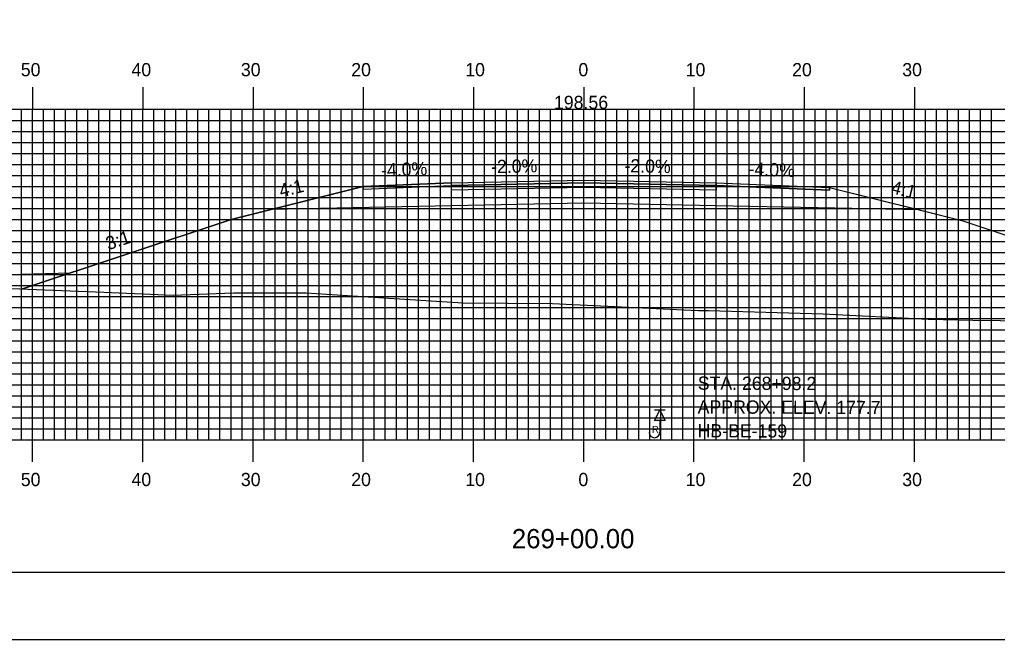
# Model space of a CAD drawing. Extents: x 1808226 to 1808569, y 442591 to 442811.
# Drawn here: x 1808340.1 to 1808428.8, y 442590.5 to 442646.8 of the extents above; entities that cross this region are included whole.
import ezdxf

# ---------------------------------------------------------------- set-up
doc = ezdxf.new("R2010")
doc.units = 0
for name, color, linetype in [('ANNOTATION', 7, 'Continuous'), ('BORDER', 7, 'Continuous'), ('BORING - REFUSAL', 7, 'Continuous'), ('D_Roadway_Centerline', 7, 'Continuous'), ('D_Roadway_Centerline_Text', 7, 'Continuous'), ('D_Roadway_Edge_Shoulder', 7, 'Continuous'), ('D_Roadway_Edge_TW', 7, 'Continuous'), ('D_Roadway_Pavement', 7, 'Continuous'), ('D_Roadway_SlopeLines', 7, 'Continuous'), ('D_Roadway_SubGrade', 7, 'Continuous'), ('H_V ANNOTATION', 7, 'Continuous'), ('MAJOR', 7, 'Continuous'), ('MINOR', 7, 'Continuous'), ('PLOT BOUNDARY', 7, 'Continuous'), ('S_Roadway_Centerline', 7, 'Continuous')]:
    doc.layers.add(name, color=color, linetype=linetype)

msp = doc.modelspace()

# ---------------------------------------------------------------- linework, layer by layer
at = {"layer": 'BORDER'}
msp.add_lwpolyline([(1808241.698, 442596.665), (1808561.698, 442596.665), (1808561.698, 442806.665), (1808241.698, 442806.665)], close=True, dxfattribs=at)
at = {"layer": 'BORING - REFUSAL'}
for p, q in [((1808398.678, 442611.365), (1808397.718, 442611.365)), ((1808398.198, 442610.406), (1808398.198, 442609.347))]:
    msp.add_line(p, q, dxfattribs=at)
msp.add_lwpolyline([(1808398.198, 442611.365), (1808398.678, 442610.406), (1808397.718, 442610.406)], close=True, dxfattribs=at)
msp.add_arc((1808397.713, 442609.347), 0.485, 180, 0, dxfattribs=at)
at = {"layer": 'D_Roadway_Centerline'}
msp.add_lwpolyline([(1808340.374, 442622.361), (1808359.298, 442628.669), (1808362.936, 442629.578), (1808371.298, 442631.669), (1808379.298, 442631.989), (1808391.298, 442632.229), (1808403.298, 442631.989), (1808413.595, 442631.577), (1808421.758, 442629.536), (1808425.595, 442628.577), (1808456.134, 442618.398)], dxfattribs=at)
at = {"layer": 'D_Roadway_Edge_Shoulder'}
for points in [[(1808379.298, 442631.989), (1808371.298, 442631.669), (1808371.298, 442631.419), (1808379.298, 442631.739)], [(1808403.298, 442631.989), (1808413.595, 442631.577), (1808413.595, 442631.327), (1808403.298, 442631.739)]]:
    msp.add_lwpolyline(points, close=True, dxfattribs=at)
at = {"layer": 'D_Roadway_Edge_TW'}
msp.add_lwpolyline([(1808379.298, 442631.739), (1808379.298, 442631.989), (1808391.298, 442632.229), (1808403.298, 442631.989), (1808403.298, 442631.739), (1808391.298, 442631.979)], close=True, dxfattribs=at)
at = {"layer": 'D_Roadway_Pavement'}
msp.add_lwpolyline([(1808379.298, 442631.322), (1808379.298, 442631.739), (1808391.298, 442631.979), (1808403.298, 442631.739), (1808403.298, 442631.322), (1808391.298, 442631.562)], close=True, dxfattribs=at)
at = {"layer": 'D_Roadway_SlopeLines'}
for points in [[(1808371.298, 442631.669), (1808359.298, 442628.669), (1808340.374, 442622.361)], [(1808413.595, 442631.577), (1808425.595, 442628.577), (1808456.134, 442618.398)], [(1808344.714, 442623.808), (1808328.23, 442623.344), (1808326.137, 442622.637)]]:
    msp.add_lwpolyline(points, dxfattribs=at)
at = {"layer": 'D_Roadway_SubGrade'}
msp.add_lwpolyline([(1808379.298, 442629.906), (1808362.936, 442629.578), (1808371.298, 442631.669), (1808371.298, 442631.419), (1808379.298, 442631.739), (1808391.298, 442631.979), (1808403.298, 442631.739), (1808413.595, 442631.327), (1808413.595, 442631.577), (1808421.758, 442629.536), (1808403.298, 442629.906), (1808391.298, 442630.146)], close=True, dxfattribs=at)
at = {"layer": 'MAJOR'}
for p, q in [((1808341.298, 442640.669), (1808341.298, 442638.665)), ((1808351.298, 442640.669), (1808351.298, 442638.665)), ((1808361.298, 442640.669), (1808361.298, 442638.665)), ((1808371.298, 442640.669), (1808371.298, 442638.665)), ((1808381.298, 442640.669), (1808381.298, 442638.665)), ((1808391.298, 442640.669), (1808391.298, 442638.665)), ((1808401.298, 442640.669), (1808401.298, 442638.665)), ((1808411.298, 442640.669), (1808411.298, 442638.665)), ((1808421.298, 442640.669), (1808421.298, 442638.665)), ((1808251.298, 442638.665), (1808531.298, 442638.665)), ((1808251.298, 442638.665), (1808531.298, 442638.665)), ((1808341.298, 442608.665), (1808341.298, 442638.665)), ((1808351.298, 442608.665), (1808351.298, 442638.665)), ((1808361.298, 442608.665), (1808361.298, 442638.665)), ((1808371.298, 442608.665), (1808371.298, 442638.665)), ((1808381.298, 442608.665), (1808381.298, 442638.665)), ((1808391.298, 442608.665), (1808391.298, 442638.665)), ((1808401.298, 442608.665), (1808401.298, 442638.665)), ((1808411.298, 442608.665), (1808411.298, 442638.665)), ((1808421.298, 442608.665), (1808421.298, 442638.665)), ((1808251.298, 442633.665), (1808531.298, 442633.665)), ((1808251.298, 442628.665), (1808531.298, 442628.665)), ((1808251.298, 442623.665), (1808531.298, 442623.665)), ((1808251.298, 442618.665), (1808531.298, 442618.665)), ((1808251.298, 442613.665), (1808531.298, 442613.665)), ((1808251.298, 442608.665), (1808531.298, 442608.665)), ((1808251.298, 442608.665), (1808531.298, 442608.665)), ((1808341.298, 442606.661), (1808341.298, 442608.665)), ((1808351.298, 442606.661), (1808351.298, 442608.665)), ((1808361.298, 442606.661), (1808361.298, 442608.665)), ((1808371.298, 442606.661), (1808371.298, 442608.665)), ((1808381.298, 442606.661), (1808381.298, 442608.665)), ((1808391.298, 442606.661), (1808391.298, 442608.665)), ((1808401.298, 442606.661), (1808401.298, 442608.665)), ((1808411.298, 442606.661), (1808411.298, 442608.665)), ((1808421.298, 442606.661), (1808421.298, 442608.665))]:
    msp.add_line(p, q, dxfattribs=at)
at = {"layer": 'MINOR'}
for p, q in [((1808340.298, 442608.665), (1808340.298, 442638.665)), ((1808342.298, 442608.665), (1808342.298, 442638.665)), ((1808343.298, 442608.665), (1808343.298, 442638.665)), ((1808344.298, 442608.665), (1808344.298, 442638.665)), ((1808345.298, 442608.665), (1808345.298, 442638.665)), ((1808346.298, 442608.665), (1808346.298, 442638.665)), ((1808347.298, 442608.665), (1808347.298, 442638.665)), ((1808348.298, 442608.665), (1808348.298, 442638.665)), ((1808349.298, 442608.665), (1808349.298, 442638.665)), ((1808350.298, 442608.665), (1808350.298, 442638.665)), ((1808352.298, 442608.665), (1808352.298, 442638.665)), ((1808353.298, 442608.665), (1808353.298, 442638.665)), ((1808354.298, 442608.665), (1808354.298, 442638.665)), ((1808355.298, 442608.665), (1808355.298, 442638.665)), ((1808356.298, 442608.665), (1808356.298, 442638.665)), ((1808357.298, 442608.665), (1808357.298, 442638.665)), ((1808358.298, 442608.665), (1808358.298, 442638.665)), ((1808359.298, 442608.665), (1808359.298, 442638.665)), ((1808360.298, 442608.665), (1808360.298, 442638.665)), ((1808362.298, 442608.665), (1808362.298, 442638.665)), ((1808363.298, 442608.665), (1808363.298, 442638.665)), ((1808364.298, 442608.665), (1808364.298, 442638.665)), ((1808365.298, 442608.665), (1808365.298, 442638.665)), ((1808366.298, 442608.665), (1808366.298, 442638.665)), ((1808367.298, 442608.665), (1808367.298, 442638.665)), ((1808368.298, 442608.665), (1808368.298, 442638.665)), ((1808369.298, 442608.665), (1808369.298, 442638.665)), ((1808370.298, 442608.665), (1808370.298, 442638.665)), ((1808372.298, 442608.665), (1808372.298, 442638.665)), ((1808373.298, 442608.665), (1808373.298, 442638.665)), ((1808374.298, 442608.665), (1808374.298, 442638.665)), ((1808375.298, 442608.665), (1808375.298, 442638.665)), ((1808376.298, 442608.665), (1808376.298, 442638.665)), ((1808377.298, 442608.665), (1808377.298, 442638.665)), ((1808378.298, 442608.665), (1808378.298, 442638.665)), ((1808379.298, 442608.665), (1808379.298, 442638.665)), ((1808380.298, 442608.665), (1808380.298, 442638.665)), ((1808382.298, 442608.665), (1808382.298, 442638.665)), ((1808383.298, 442608.665), (1808383.298, 442638.665)), ((1808384.298, 442608.665), (1808384.298, 442638.665)), ((1808385.298, 442608.665), (1808385.298, 442638.665)), ((1808386.298, 442608.665), (1808386.298, 442638.665)), ((1808387.298, 442608.665), (1808387.298, 442638.665)), ((1808388.298, 442608.665), (1808388.298, 442638.665)), ((1808389.298, 442608.665), (1808389.298, 442638.665)), ((1808390.298, 442608.665), (1808390.298, 442638.665)), ((1808392.298, 442608.665), (1808392.298, 442638.665)), ((1808393.298, 442608.665), (1808393.298, 442638.665)), ((1808394.298, 442608.665), (1808394.298, 442638.665)), ((1808395.298, 442608.665), (1808395.298, 442638.665)), ((1808396.298, 442608.665), (1808396.298, 442638.665)), ((1808397.298, 442608.665), (1808397.298, 442638.665)), ((1808398.298, 442608.665), (1808398.298, 442638.665)), ((1808399.298, 442608.665), (1808399.298, 442638.665)), ((1808400.298, 442608.665), (1808400.298, 442638.665)), ((1808402.298, 442608.665), (1808402.298, 442638.665)), ((1808403.298, 442608.665), (1808403.298, 442638.665)), ((1808404.298, 442608.665), (1808404.298, 442638.665)), ((1808405.298, 442608.665), (1808405.298, 442638.665)), ((1808406.298, 442608.665), (1808406.298, 442638.665)), ((1808407.298, 442608.665), (1808407.298, 442638.665)), ((1808408.298, 442608.665), (1808408.298, 442638.665)), ((1808409.298, 442608.665), (1808409.298, 442638.665)), ((1808410.298, 442608.665), (1808410.298, 442638.665)), ((1808412.298, 442608.665), (1808412.298, 442638.665)), ((1808413.298, 442608.665), (1808413.298, 442638.665)), ((1808414.298, 442608.665), (1808414.298, 442638.665)), ((1808415.298, 442608.665), (1808415.298, 442638.665)), ((1808416.298, 442608.665), (1808416.298, 442638.665)), ((1808417.298, 442608.665), (1808417.298, 442638.665)), ((1808418.298, 442608.665), (1808418.298, 442638.665)), ((1808419.298, 442608.665), (1808419.298, 442638.665)), ((1808420.298, 442608.665), (1808420.298, 442638.665)), ((1808422.298, 442608.665), (1808422.298, 442638.665)), ((1808423.298, 442608.665), (1808423.298, 442638.665)), ((1808424.298, 442608.665), (1808424.298, 442638.665)), ((1808425.298, 442608.665), (1808425.298, 442638.665)), ((1808426.298, 442608.665), (1808426.298, 442638.665)), ((1808427.298, 442608.665), (1808427.298, 442638.665)), ((1808428.298, 442608.665), (1808428.298, 442638.665)), ((1808251.298, 442637.665), (1808531.298, 442637.665)), ((1808251.298, 442636.665), (1808531.298, 442636.665)), ((1808251.298, 442635.665), (1808531.298, 442635.665)), ((1808251.298, 442634.665), (1808531.298, 442634.665)), ((1808251.298, 442632.665), (1808531.298, 442632.665)), ((1808251.298, 442631.665), (1808531.298, 442631.665)), ((1808251.298, 442630.665), (1808531.298, 442630.665)), ((1808251.298, 442629.665), (1808531.298, 442629.665)), ((1808251.298, 442627.665), (1808531.298, 442627.665)), ((1808251.298, 442626.665), (1808531.298, 442626.665)), ((1808251.298, 442625.665), (1808531.298, 442625.665)), ((1808251.298, 442624.665), (1808531.298, 442624.665)), ((1808251.298, 442622.665), (1808531.298, 442622.665)), ((1808251.298, 442621.665), (1808531.298, 442621.665)), ((1808251.298, 442620.665), (1808531.298, 442620.665)), ((1808251.298, 442619.665), (1808531.298, 442619.665)), ((1808251.298, 442617.665), (1808531.298, 442617.665)), ((1808251.298, 442616.665), (1808531.298, 442616.665)), ((1808251.298, 442615.665), (1808531.298, 442615.665)), ((1808251.298, 442614.665), (1808531.298, 442614.665)), ((1808251.298, 442612.665), (1808531.298, 442612.665)), ((1808251.298, 442611.665), (1808531.298, 442611.665)), ((1808251.298, 442610.665), (1808531.298, 442610.665)), ((1808251.298, 442609.665), (1808531.298, 442609.665))]:
    msp.add_line(p, q, dxfattribs=at)
at = {"layer": 'PLOT BOUNDARY'}
msp.add_lwpolyline([(1808225.511, 442590.547), (1808565.511, 442590.547), (1808565.511, 442810.547), (1808225.511, 442810.547)], close=True, dxfattribs=at)
at = {"layer": 'S_Roadway_Centerline'}
msp.add_lwpolyline([(1808337.804, 442622.458), (1808347.763, 442622.083), (1808354.057, 442621.804), (1808359.536, 442621.999), (1808366.119, 442622.008), (1808373.623, 442621.518), (1808380.371, 442621.098), (1808388.458, 442621.045), (1808400.385, 442620.47), (1808401.721, 442620.409), (1808402.615, 442620.401), (1808413.034, 442620.104), (1808422.558, 442619.607), (1808426.596, 442619.54), (1808436.673, 442619.411), (1808445.116, 442618.894), (1808452.182, 442618.481), (1808465.518, 442618.2), (1808476.656, 442618.414), (1808486.351, 442618.327)], dxfattribs=at)

# ---------------------------------------------------------------- texts
at = {"layer": 'ANNOTATION'}
for s, rotation, p in [('-4.0%', 2.29061, (1808372.93, 442632.536)), ('-2.0%', 1.14576, (1808382.904, 442632.862)), ('-2.0%', 358.85424, (1808394.984, 442632.956)), ('-4.0%', 357.70939, (1808406.238, 442632.673)), ('4:1', 14.03624, (1808363.834, 442630.664)), ('4:1', 345.96376, (1808419.101, 442631.062)), ('3:1', 18.43478, (1808348.175, 442625.869))]:
    msp.add_text(s, height=1.2, rotation=rotation, dxfattribs=at).set_placement(p)
at = {"layer": 'BORING - REFUSAL'}
for s, p in [('STA. 268+98.2', (1808401.642, 442613.214)), ('APPROX. ELEV. 177.7', (1808401.635, 442611.054)), ('HB-BE-159', (1808401.628, 442608.894))]:
    msp.add_text(s, height=1.2, rotation=359.81416, dxfattribs=at).set_placement(p)
msp.add_text('R', height=0.64, dxfattribs=at).set_placement((1808397.489, 442609.291))
at = {"layer": 'D_Roadway_Centerline'}
for s, p in [('C', (1808391.293, 442632.229)), ('L', (1808391.298, 442632.222))]:
    msp.add_text(s, height=0.0146, dxfattribs=at).set_placement(p)
at = {"layer": 'D_Roadway_Centerline_Text'}
msp.add_text('198.56', height=1.2, dxfattribs=at).set_placement((1808388.601, 442638.692))
at = {"layer": 'H_V ANNOTATION'}
for s, height, p in [('50', 1.2, (1808340.227, 442641.665)), ('40', 1.2, (1808350.27, 442641.665)), ('30', 1.2, (1808360.195, 442641.665)), ('20', 1.2, (1808370.206, 442641.665)), ('10', 1.2, (1808380.549, 442641.665)), ('0', 1.2, (1808390.816, 442641.665)), ('10', 1.2, (1808400.549, 442641.665)), ('20', 1.2, (1808410.206, 442641.665)), ('30', 1.2, (1808420.195, 442641.665)), ('50', 1.2, (1808340.227, 442604.465)), ('40', 1.2, (1808350.27, 442604.465)), ('30', 1.2, (1808360.195, 442604.465)), ('20', 1.2, (1808370.206, 442604.465)), ('10', 1.2, (1808380.549, 442604.465)), ('0', 1.2, (1808390.816, 442604.465)), ('10', 1.2, (1808400.549, 442604.465)), ('20', 1.2, (1808410.206, 442604.465)), ('30', 1.2, (1808420.195, 442604.465)), ('269+00.00', 1.75, (1808384.775, 442598.821))]:
    msp.add_text(s, height=height, dxfattribs=at).set_placement(p)

doc.saveas('drawing.dxf')
